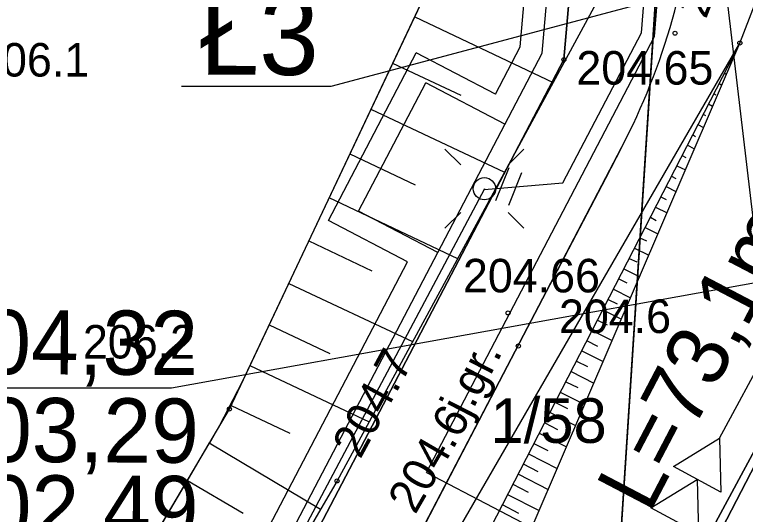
# Model space of a CAD drawing. Extents: x 6512606 to 6513347, y 6022524 to 6022728.
# Drawn here: x 6512715.61 to 6512731.97, y 6022599.67 to 6022610.86 of the extents above; entities that cross this region are included whole.
import ezdxf

# ---------------------------------------------------------------- set-up
doc = ezdxf.new("R2010")
doc.units = 0
for name, color, linetype in [('000 Inne (niezydentyfikowane)', 7, 'Continuous'), ('20', 7, 'Continuous'), ('203-punkt graniczny', 7, 'Continuous'), ('211-numer działki ewidencyjnej', 7, 'Continuous'), ('217-kontur klasyfikacyjny', 7, 'Continuous'), ('218-kontur użytku gruntowego', 7, 'Continuous'), ('219-działka ewidencyjna', 7, 'Continuous'), ('4', 7, 'Continuous'), ('Default', 7, 'Continuous'), ('E_OSW_KABLE', 7, 'Continuous'), ('jezdnia', 7, 'Continuous'), ('jezdnia-Atr17', 7, 'Continuous'), ('kolor_kostka_bet', 7, 'Continuous'), ('kolor_sc_rowerowa', 7, 'Continuous'), ('latarnia', 7, 'Continuous'), ('Level 47', 7, 'Continuous'), ('maxp_kan_deszczowa', 7, 'Continuous'), ('maxp_obrzeże', 7, 'Continuous'), ('maxp_ramka_2', 7, 'Continuous'), ('ogrodzenie trwałe', 7, 'Continuous'), ('pikieta naturalna', 7, 'Continuous'), ('pikieta naturalna-Atr2', 7, 'Continuous'), ('pikieta sztuczna', 7, 'Continuous'), ('pikieta sztuczna-Atr2', 7, 'Continuous'), ('przewód elektroenergetyczny (linia)', 7, 'Continuous'), ('punkt wysokościowy naturalny-Atr2', 7, 'Continuous'), ('skarpa nieumocniona', 7, 'Continuous'), ('zadrzewienie  zakrzewienie', 7, 'Continuous')]:
    doc.layers.add(name, color=color, linetype=linetype)

# ---------------------------------------------------------------- blocks, each defined once
blk = doc.blocks.new('203')
at = {"layer": 'Default'}
blk.add_circle((0, 0), 0.45, dxfattribs=at)
blk = doc.blocks.new('PW01')
at = {"layer": 'Default'}
blk.add_circle((0, 0), 0.45, dxfattribs=at)
blk = doc.blocks.new('SM01')
at = {"layer": 'Default'}
for p, q in [((-5.3, 5.31), (-8.83, 8.84)), ((5.31, 5.31), (8.84, 8.84)), ((-5.3, -5.3), (-8.83, -8.83)), ((5.31, -5.3), (8.84, -8.83))]:
    blk.add_line(p, q, dxfattribs=at)
blk.add_circle((0, 0), 2.5, dxfattribs=at)

msp = doc.modelspace()

# ---------------------------------------------------------------- linework, layer by layer
at = {"layer": '000 Inne (niezydentyfikowane)'}
for p, q in [((6512724.57, 6022610.81), (6512727.67, 6022609.34)), ((6512724.07, 6022609.77), (6512725.6, 6022609.05)), ((6512723.59, 6022608.74), (6512726.58, 6022607.33)), ((6512723.12, 6022607.74), (6512724.58, 6022607.05)), ((6512722.65, 6022606.76), (6512725.53, 6022605.4)), ((6512722.2, 6022605.79), (6512723.61, 6022605.12)), ((6512721.75, 6022604.84), (6512724.52, 6022603.54)), ((6512721.31, 6022603.91), (6512722.67, 6022603.27)), ((6512720.88, 6022603), (6512723.55, 6022601.74)), ((6512720.46, 6022602.11), (6512721.77, 6022601.49)), ((6512719.97, 6022601.27), (6512722.46, 6022599.79)), ((6512719.48, 6022600.43), (6512720.73, 6022599.7))]:
    msp.add_line(p, q, dxfattribs=at)
for points in [[(6512731.62, 6022609.78), (6512731.65, 6022609.76)], [(6512731.5, 6022609.55), (6512731.53, 6022609.53)], [(6512731.38, 6022609.32), (6512731.45, 6022609.28)], [(6512731.27, 6022609.09), (6512731.31, 6022609.06)], [(6512731.15, 6022608.86), (6512731.24, 6022608.81)], [(6512731.03, 6022608.63), (6512731.08, 6022608.6)], [(6512730.91, 6022608.4), (6512731.04, 6022608.33)], [(6512730.79, 6022608.17), (6512730.86, 6022608.13)], [(6512730.67, 6022607.94), (6512730.83, 6022607.85)], [(6512730.56, 6022607.7), (6512730.64, 6022607.66)], [(6512730.44, 6022607.47), (6512730.63, 6022607.38)], [(6512730.32, 6022607.24), (6512730.42, 6022607.19)], [(6512730.2, 6022607.01), (6512730.42, 6022606.9)], [(6512730.08, 6022606.78), (6512730.2, 6022606.72)], [(6512729.96, 6022606.55), (6512730.22, 6022606.42)], [(6512729.85, 6022606.32), (6512729.98, 6022606.25)], [(6512729.73, 6022606.09), (6512730.01, 6022605.95)], [(6512729.61, 6022605.86), (6512729.76, 6022605.79)], [(6512729.49, 6022605.63), (6512729.81, 6022605.47)], [(6512729.37, 6022605.4), (6512729.54, 6022605.32)], [(6512729.25, 6022605.17), (6512729.61, 6022604.99)], [(6512729.14, 6022604.94), (6512729.32, 6022604.85)], [(6512729.02, 6022604.71), (6512729.4, 6022604.52)], [(6512728.9, 6022604.48), (6512729.1, 6022604.38)], [(6512728.78, 6022604.25), (6512729.2, 6022604.04)], [(6512728.66, 6022604.02), (6512728.88, 6022603.91)], [(6512728.54, 6022603.79), (6512728.99, 6022603.56)], [(6512728.42, 6022603.56), (6512728.66, 6022603.44)], [(6512728.31, 6022603.33), (6512728.79, 6022603.09)], [(6512728.19, 6022603.1), (6512728.44, 6022602.98)], [(6512728.07, 6022602.87), (6512728.58, 6022602.61)], [(6512727.95, 6022602.64), (6512728.22, 6022602.51)], [(6512727.83, 6022602.41), (6512728.38, 6022602.13)], [(6512727.71, 6022602.18), (6512727.99, 6022602.04)], [(6512727.6, 6022601.95), (6512728.17, 6022601.66)], [(6512727.48, 6022601.72), (6512727.77, 6022601.57)], [(6512727.36, 6022601.49), (6512727.97, 6022601.18)], [(6512727.24, 6022601.26), (6512727.55, 6022601.1)], [(6512727.12, 6022601.03), (6512727.76, 6022600.7)], [(6512727, 6022600.8), (6512727.33, 6022600.63)], [(6512726.89, 6022600.57), (6512727.56, 6022600.23)], [(6512726.77, 6022600.35), (6512727.11, 6022600.17)], [(6512726.65, 6022600.12), (6512727.36, 6022599.76)], [(6512726.53, 6022599.89), (6512726.89, 6022599.7)]]:
    msp.add_lwpolyline(points, dxfattribs=at)
at = {"layer": '20'}
for p, q in [((6512731.52, 6022611.602), (6512722.692, 6022609.245)), ((6512722.692, 6022609.245), (6512719.347, 6022609.245)), ((6512739.016, 6022606.082), (6512719.123, 6022602.5)), ((6512719.123, 6022602.5), (6512713.546, 6022602.5))]:
    msp.add_line(p, q, dxfattribs=at)
at = {"layer": '217-kontur klasyfikacyjny'}
for points in [[(6512727.91, 6022609.85), (6512729.5, 6022628.07)], [(6512716.29, 6022587.65), (6512727.91, 6022609.85)], [(6512735.75, 6022607.64), (6512728.87, 6022594.38)]]:
    msp.add_lwpolyline(points, dxfattribs=at)
at = {"layer": '218-kontur użytku gruntowego'}
for points in [[(6512728.87, 6022594.38), (6512731.57, 6022636.01)], [(6512731.57, 6022636.01), (6512728.87, 6022594.38)], [(6512729.5, 6022628.07), (6512727.91, 6022609.85)], [(6512727.91, 6022609.85), (6512729.5, 6022628.07)], [(6512727.91, 6022609.85), (6512716.29, 6022587.65)], [(6512716.29, 6022587.65), (6512727.91, 6022609.85)], [(6512735.75, 6022607.64), (6512728.87, 6022594.38)], [(6512728.87, 6022594.38), (6512735.75, 6022607.64)]]:
    msp.add_lwpolyline(points, dxfattribs=at)
at = {"layer": '219-działka ewidencyjna'}
for points in [[(6512727.91, 6022609.85), (6512731.23, 6022647.88)], [(6512728.87, 6022594.38), (6512732.3, 6022647.29)], [(6512716.29, 6022587.65), (6512727.91, 6022609.85)], [(6512735.75, 6022607.64), (6512728.87, 6022594.38)]]:
    msp.add_lwpolyline(points, dxfattribs=at)
at = {"layer": '4'}
for points in [[(6512727.91, 6022609.85), (6512731.23, 6022647.88)], [(6512728.87, 6022594.38), (6512732.3, 6022647.29)], [(6512716.29, 6022587.65), (6512727.91, 6022609.85)], [(6512735.75, 6022607.64), (6512728.87, 6022594.38)]]:
    msp.add_lwpolyline(points, dxfattribs=at)
at = {"layer": 'E_OSW_KABLE'}
for p, q in [((6512726.676, 6022607.425), (6512726.381, 6022606.69)), ((6512726.963, 6022607.317), (6512726.669, 6022606.582)), ((6512726.121, 6022606.942), (6512727.887, 6022607.088))]:
    msp.add_line(p, q, dxfattribs=at)
for points in [[(6512724.836, 6022600.607), (6512729.94, 6022610.367), (6512731.171, 6022625.931), (6512732.446, 6022645.898), (6512731.748, 6022646.801), (6512731.905, 6022652.094)], [(6512727.887, 6022607.088), (6512729.646, 6022610.451), (6512730.846, 6022625.624), (6512731.171, 6022625.931)], [(6512724.836, 6022600.607), (6512735.232, 6022595.177), (6512735.232, 6022595.177)]]:
    msp.add_lwpolyline(points, dxfattribs=at)
at = {"layer": 'jezdnia'}
msp.add_lwpolyline([(6512731.08, 6022620.65), (6512728.82, 6022611.46), (6512722.83, 6022600.42), (6512717.94, 6022592.02), (6512712.43, 6022580.37), (6512709.04, 6022573), (6512712.21, 6022570.83), (6512715.01, 6022579.3), (6512720.33, 6022590.74), (6512725.35, 6022598.98), (6512731.85, 6022610.22), (6512735.75, 6022620.3)], close=True, dxfattribs=at)
at = {"layer": 'kolor_kostka_bet'}
for p, q in [((6512731.23, 6022647.88), (6512727.91, 6022609.85)), ((6512727.91, 6022609.85), (6512727.9, 6022609.778))]:
    msp.add_line(p, q, dxfattribs=at)
for points in [[(6512708.915, 6022572.782), (6512706.28, 6022574.16), (6512716.29, 6022587.65), (6512727.91, 6022609.85), (6512731.23, 6022647.88), (6512731.197, 6022649.415), (6512729.023, 6022649.531)], [(6512729.023, 6022649.531), (6512731.197, 6022649.415), (6512731.23, 6022647.88), (6512727.91, 6022609.85), (6512716.29, 6022587.65), (6512706.28, 6022574.16), (6512708.915, 6022572.782)], [(6512718.619, 6022587.623), (6512719.35, 6022589.023), (6512723.817, 6022597.575), (6512727.095, 6022603.851), (6512728.84, 6022607.192), (6512729.199, 6022607.879)]]:
    msp.add_lwpolyline(points, dxfattribs=at)
msp.add_arc((6512715.903, 6022614.824), 15, 332.4212, 356.0865, dxfattribs=at)
at = {"layer": 'kolor_sc_rowerowa'}
msp.add_lwpolyline([(6512729.199, 6022607.879), (6512728.84, 6022607.192), (6512727.095, 6022603.851), (6512723.817, 6022597.575), (6512719.35, 6022589.023), (6512718.619, 6022587.623)], dxfattribs=at)
msp.add_arc((6512715.903, 6022614.824), 15, 332.4212, 356.0865, dxfattribs=at)
at = {"layer": 'maxp_kan_deszczowa'}
for points in [[(6512725.335, 6022612.434), (6512724.242, 6022610.122), (6512720.701, 6022602.625), (6512720.201, 6022601.66), (6512719.972, 6022601.269), (6512719.97, 6022601.276), (6512719.518, 6022600.503), (6512718.485, 6022598.756), (6512717.786, 6022597.573), (6512717.004, 6022596.25), (6512716.459, 6022595.327), (6512716.038, 6022594.614), (6512715.257, 6022593.294), (6512714.873, 6022592.662), (6512714.556, 6022592.225), (6512713.769, 6022591.139), (6512713.152, 6022590.289), (6512712.768, 6022589.76), (6512711.747, 6022588.353), (6512710.95, 6022587.254), (6512708.754, 6022584.227)], [(6512731.394, 6022601.378), (6512732.494, 6022603.407), (6512731.52, 6022611.602)]]:
    msp.add_lwpolyline(points, dxfattribs=at)
for points in [[(6512730.361, 6022600.744), (6512731.394, 6022601.378), (6512731.427, 6022600.166)], [(6512729.86, 6022599.821), (6512730.894, 6022600.455), (6512730.926, 6022599.243)]]:
    msp.add_lwpolyline(points, close=True, dxfattribs=at)
at = {"layer": 'maxp_obrzeże'}
msp.add_line((6512718.619, 6022587.623), (6512729.199, 6022607.879), dxfattribs=at)
msp.add_arc((6512715.903, 6022614.824), 15, 332.4212, 356.0865, dxfattribs=at)
at = {"layer": 'maxp_ramka_2'}
for p, q in [((6512722.638, 6022606.247), (6512724.605, 6022610.004)), ((6512726.376, 6022609.077), (6512724.605, 6022610.004)), ((6512726.588, 6022608.402), (6512724.816, 6022609.329)), ((6512725.085, 6022605.531), (6512723.313, 6022606.458)), ((6512724.41, 6022605.32), (6512722.638, 6022606.247))]:
    msp.add_line(p, q, dxfattribs=at)
for points in [[(6512721.086, 6022597.89), (6512727.421, 6022609.993), (6512730.73, 6022647.896), (6512730.304, 6022667.864), (6512724.475, 6022673.519)], [(6512726.376, 6022609.077), (6512726.931, 6022610.136), (6512728.87, 6022632.35)], [(6512723.313, 6022606.458), (6512724.816, 6022609.329)], [(6512704.78, 6022573.816), (6512715.44, 6022588.183), (6512724.41, 6022605.32)]]:
    msp.add_lwpolyline(points, dxfattribs=at)
at = {"layer": 'ogrodzenie trwałe'}
msp.add_lwpolyline([(6512755.94, 6022562.73), (6512746.11, 6022568.85), (6512734.85, 6022575.76), (6512722.94, 6022583.56), (6512729.52, 6022596.18), (6512735.87, 6022607.95), (6512736.94, 6022619.99)], dxfattribs=at)
at = {"layer": 'przewód elektroenergetyczny (linia)'}
msp.add_lwpolyline([(6512726.13, 6022606.96), (6512716.02, 6022587.92), (6512710.36, 6022581.04), (6512708.56, 6022578.24), (6512706.34, 6022574.34), (6512697.643, 6022555.92)], dxfattribs=at)
at = {"layer": 'skarpa nieumocniona'}
for points in [[(6512728.82, 6022611.46), (6512722.83, 6022600.42), (6512717.94, 6022592.02), (6512712.43, 6022580.37), (6512701.7, 6022566.06), (6512698.57, 6022561.61), (6512695.94, 6022556.8), (6512692.31, 6022558.67), (6512695.23, 6022563.7), (6512698.61, 6022570.74), (6512708.72, 6022584.18), (6512714.93, 6022592.74), (6512720.42, 6022602.03), (6512725.72, 6022613.25), (6512727.1, 6022620.51), (6512731.08, 6022620.65)], [(6512728.82, 6022611.46), (6512722.83, 6022600.42), (6512717.94, 6022592.02), (6512712.43, 6022580.37), (6512701.7, 6022566.06), (6512698.57, 6022561.61), (6512695.94, 6022556.8), (6512692.31, 6022558.67), (6512695.23, 6022563.7), (6512698.61, 6022570.74), (6512708.72, 6022584.18), (6512714.93, 6022592.74), (6512720.42, 6022602.03), (6512725.72, 6022613.25), (6512727.1, 6022620.51), (6512731.08, 6022620.65)], [(6512731.85, 6022610.22), (6512725.87, 6022598.6), (6512720.88, 6022590.45), (6512715.64, 6022578.67), (6512716.84, 6022579.11), (6512721.8, 6022590.03), (6512726.68, 6022598.18)], [(6512731.85, 6022610.22), (6512725.87, 6022598.6), (6512720.88, 6022590.45), (6512715.64, 6022578.67), (6512716.84, 6022579.11), (6512721.8, 6022590.03), (6512726.68, 6022598.18)]]:
    msp.add_lwpolyline(points, close=True, dxfattribs=at)
at = {"layer": 'zadrzewienie  zakrzewienie'}
msp.add_lwpolyline([(6512735.87, 6022607.95), (6512729.52, 6022596.18), (6512722.94, 6022583.56), (6512734.85, 6022575.76)], dxfattribs=at)

# ---------------------------------------------------------------- block references
at = {"layer": '203-punkt graniczny', "xscale": 0.1, "yscale": 0.10000000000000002}
msp.add_blockref('203', (6512727.91, 6022609.85), dxfattribs=at)
at = {"layer": 'latarnia', "xscale": 0.1, "yscale": 0.10000000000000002}
msp.add_blockref('SM01', (6512726.13, 6022606.96), dxfattribs=at)
at = {"layer": 'pikieta naturalna', "xscale": 0.1, "yscale": 0.10000000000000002}
for p in [(6512731.85, 6022610.22), (6512726.66, 6022604.18), (6512720.42, 6022602.03), (6512722.83, 6022600.42)]:
    msp.add_blockref('PW01', p, dxfattribs=at)
at = {"layer": 'pikieta sztuczna', "xscale": 0.1, "yscale": 0.10000000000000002}
for p in [(6512730.4, 6022610.44), (6512726.89, 6022603.44)]:
    msp.add_blockref('PW01', p, dxfattribs=at)

# ---------------------------------------------------------------- texts
at = {"layer": '211-numer działki ewidencyjnej'}
msp.add_text('1/58', height=1, dxfattribs=at).set_placement((6512726.266, 6022601.272))
at = {"layer": 'jezdnia-Atr17'}
msp.add_text('j.gr.', height=0.75, rotation=62.768, dxfattribs=at).set_placement((6512725.78, 6022601.82))
at = {"layer": 'Level 47'}
for s, height, rotation, p in [('Ł3', 1.7971, 359.7281, (6512719.747, 6022609.515)), ('%%c75PP, L=73,1m', 1.3824, 62.3574, (6512726.582, 6022593.48)), ('204,32', 1.4377, 359.7281, (6512713.835, 6022602.816)), ('203,29', 1.4377, 359.7281, (6512713.853, 6022600.852)), ('202,49', 1.4377, 359.7281, (6512713.845, 6022599.12))]:
    msp.add_text(s, height=height, rotation=rotation, dxfattribs=at).set_placement(p)
at = {"layer": 'pikieta naturalna-Atr2'}
for s, rotation, p in [('204.5', 68.848, (6512731.09, 6022610.74)), ('204.7', 61.517, (6512723.35, 6022600.89)), ('204.6', 59.96, (6512724.58, 6022599.65))]:
    msp.add_text(s, height=0.75, rotation=rotation, dxfattribs=at).set_placement(p)
for s, p in [('204.6', (6512727.8, 6022603.73)), ('206.2', (6512717.14, 6022603.16))]:
    msp.add_text(s, height=0.75, dxfattribs=at).set_placement(p)
at = {"layer": 'pikieta sztuczna-Atr2'}
for s, p in [('204.65', (6512728.19, 6022609.29)), ('204.66', (6512725.65, 6022604.64))]:
    msp.add_text(s, height=0.75, dxfattribs=at).set_placement(p)
at = {"layer": 'punkt wysokościowy naturalny-Atr2'}
msp.add_text('206.1', height=0.75, dxfattribs=at).set_placement((6512714.77, 6022609.47))

doc.saveas('drawing.dxf')
